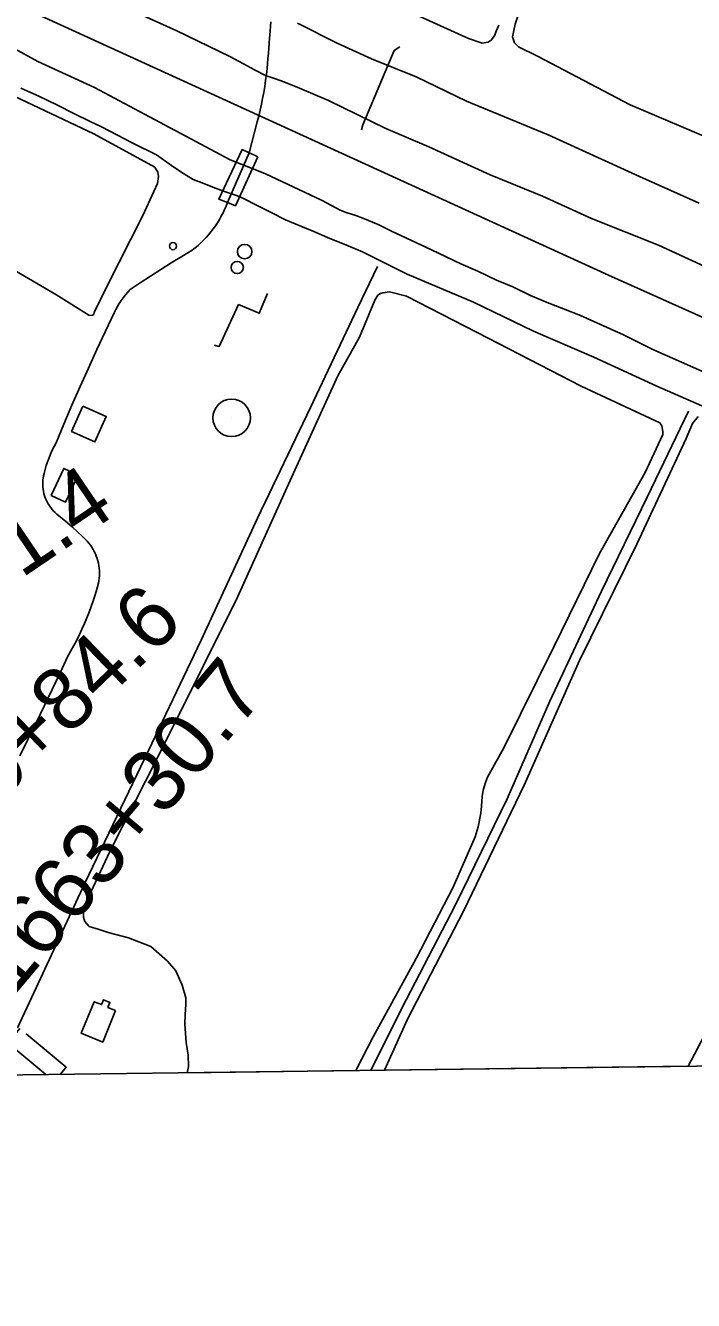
# Model space of a CAD drawing. Extents: x 3734862 to 3772949, y 391520 to 417239.
# Drawn here: x 3766771 to 3767838, y 396853 to 398891 of the extents above; entities that cross this region are included whole.
import ezdxf

# ---------------------------------------------------------------- set-up
doc = ezdxf.new("R2010")
doc.units = 0
for name, color, linetype in [('V-BLDG-OTLN', 7, 'Continuous'), ('V-BRDG-OTLN', 7, 'Continuous'), ('V-DOMW-TANK', 7, 'Continuous'), ('V-GRID-FRAM', 7, 'Continuous'), ('V-LEVE-TOET', 7, 'Continuous'), ('V-ROAD-CNTR', 7, 'Continuous'), ('V-SITE-VEGE', 7, 'Continuous'), ('V-SURV-IDEN', 7, 'Continuous'), ('V-TOPO-SHOR', 7, 'Continuous'), ('V-TOPO-TOWR', 7, 'Continuous'), ('V-UTIL-LINE', 7, 'Continuous')]:
    doc.layers.add(name, color=color, linetype=linetype)

msp = doc.modelspace()

# ---------------------------------------------------------------- linework, layer by layer
at = {"layer": 'V-BLDG-OTLN'}
for points in [[(3766862.7, 398282.6), (3766900, 398266.1), (3766882, 398225.3), (3766844.6, 398241.9)], [(3766855.1, 398172.3), (3766835, 398129), (3766812.1, 398139.7), (3766832.2, 398183)], [(3766915.1, 397316.2), (3766894.4, 397265.8), (3766860.1, 397279.9), (3766880.9, 397330.5), (3766892.4, 397325.8), (3766895.6, 397333.5), (3766906, 397329.3), (3766902.7, 397321.3)]]:
    msp.add_lwpolyline(points, close=True, dxfattribs=at)
at = {"layer": 'V-BRDG-OTLN'}
msp.add_line((3767093.8, 398607.7), (3767128.5, 398687.3), dxfattribs=at)
msp.add_lwpolyline([(3767142.5, 398680.9), (3767106.7, 398602.6), (3767093.8, 398607.7), (3767080.2, 398613.1), (3767117.1, 398692.5), (3767128.5, 398687.3), (3767138.1, 398683)], close=True, dxfattribs=at)
at = {"layer": 'V-DOMW-TANK'}
for centre, radius in [((3767006.7, 398538.2), 5.76), ((3767121.2, 398529.4), 11.6), ((3767109.4, 398504), 9.76)]:
    msp.add_circle(centre, radius, dxfattribs=at)
at = {"layer": 'V-GRID-FRAM'}
msp.add_lwpolyline([(3738832.3, 415033.8), (3770599.2, 415447.4), (3770843.8, 397266.6), (3739061.1, 396852.8), (3738832.3, 415033.8)], dxfattribs=at)
at = {"layer": 'V-LEVE-TOET'}
for points in [[(3766947.7, 398911.8), (3767012.6, 398882.2), (3767097.3, 398841.1), (3767119.5, 398829.7), (3767136.9, 398819.8), (3767155.7, 398810.6), (3767165.6, 398807.1), (3767181.4, 398802), (3767208.7, 398790.9), (3767255, 398771.2), (3767346.8, 398726.2), (3767415.6, 398697), (3767513.4, 398652.4), (3767596.9, 398618), (3767675.6, 398582.5), (3767782.4, 398539.5), (3767884.1, 398492.9)], [(3767205.5, 398894.7), (3767269.2, 398862.4), (3767323.8, 398837.5), (3767395, 398808.7), (3767475.7, 398770), (3767605.9, 398716), (3767751.9, 398649.6), (3767847.3, 398607)]]:
    msp.add_lwpolyline(points, dxfattribs=at)
at = {"layer": 'V-ROAD-CNTR'}
for points in [[(3765561.3, 399764.9), (3765755.5, 399602.6), (3766144.5, 399300.8), (3766783.9, 398911.4), (3767702.3, 398491.7), (3768862.8, 397971.9), (3769048, 397895.2), (3769757.8, 397573.5), (3770042.5, 397441.9), (3770082, 397419.9), (3770108.8, 397401), (3770359.7, 397267.3)], [(3767162.9, 398896.6), (3767161.5, 398875.2), (3767161.1, 398870.8), (3767160.5, 398862.6), (3767159.8, 398854.4), (3767159.2, 398846.3), (3767158.5, 398838.1), (3767157.8, 398830), (3767157, 398822), (3767155.9, 398812.4), (3767155.7, 398810.6), (3767154.6, 398802.9), (3767153.2, 398793.4), (3767151.6, 398783.9), (3767149.8, 398774.4), (3767147.9, 398765), (3767145.9, 398755.5), (3767143.6, 398746.1), (3767141.2, 398736.8), (3767128.5, 398687.3), (3767093.8, 398607.7), (3767091.6, 398602.1), (3767089.2, 398596.6), (3767086.7, 398591.2), (3767083.9, 398585.9), (3767081, 398580.7), (3767077.8, 398575.5), (3767074.5, 398570.5), (3767071.1, 398565.6), (3767067.4, 398560.9), (3767063.6, 398556.3), (3767059.6, 398551.8), (3767055.5, 398547.5), (3767051.2, 398543.3), (3767046.7, 398539.2), (3767042.1, 398535.4), (3767037.4, 398531.7), (3767020.6, 398521.6), (3767003.9, 398511.4), (3766987.4, 398500.9), (3766970.9, 398490.3), (3766954.5, 398479.6), (3766938.3, 398468.6), (3766934.5, 398464.5), (3766930.8, 398460.2), (3766927.3, 398455.8), (3766924, 398451.2)], [(3766758.1, 397288.7), (3766784.3, 397344.6), (3766866.1, 397519.9), (3766961.5, 397719.5), (3767051.6, 397908.5), (3767141.7, 398103.4), (3767226.5, 398280.4), (3767302.3, 398440.3), (3767333.2, 398505.6)], [(3766924, 398451.2), (3766920.9, 398446.5), (3766918, 398441.7), (3766915.3, 398436.8), (3766912.8, 398431.8), (3766898.8, 398402.4), (3766885, 398372.9), (3766871.5, 398343.3), (3766858.2, 398313.6), (3766845.1, 398283.8), (3766832.3, 398253.8), (3766819.8, 398223.8), (3766816.7, 398217.9), (3766813.8, 398212), (3766811.1, 398205.9), (3766808.6, 398199.8), (3766806.4, 398193.6), (3766804.3, 398187.3), (3766802.4, 398180.9), (3766800.8, 398174.5), (3766800, 398171), (3766799.4, 398167.5), (3766798.9, 398164), (3766798.7, 398160.4), (3766798.7, 398156.8), (3766798.9, 398153.2), (3766799.2, 398149.7), (3766799.8, 398146.2), (3766800.6, 398142.7), (3766801.6, 398139.2), (3766802.7, 398135.8), (3766804.1, 398132.5), (3766805.6, 398129.3), (3766807.3, 398126.2)], [(3767323, 397220.8), (3767379.3, 397333.3), (3767458, 397485.1), (3767540.8, 397654.7), (3767608.9, 397810.7), (3767691.1, 397986.9), (3767764.5, 398136.9), (3767830.1, 398274.5)], [(3766807.3, 398126.2), (3766809.2, 398123.1), (3766811.3, 398120.2), (3766813.5, 398117.4), (3766815.9, 398114.7), (3766818.4, 398112.2), (3766821.1, 398109.8), (3766829.5, 398103), (3766837.9, 398096), (3766846.1, 398088.9), (3766854.1, 398081.6), (3766862.1, 398074.1), (3766869.8, 398066.5), (3766872.4, 398063.4), (3766874.8, 398060.2), (3766877, 398056.9), (3766879.1, 398053.5), (3766881, 398050), (3766882.7, 398046.4), (3766884.2, 398042.7), (3766885.6, 398038.9), (3766886.7, 398035.1), (3766887.6, 398031.2), (3766888.4, 398027.2), (3766888.9, 398023.3), (3766889.2, 398019.3), (3766889.3, 398015.3), (3766889.2, 398011.3), (3766888.9, 398007.3), (3766888.4, 398003.3), (3766887.7, 397999.4), (3766885.1, 397990), (3766882.3, 397980.6), (3766879.3, 397971.3), (3766876.1, 397962.1), (3766872.7, 397953), (3766869.1, 397943.9), (3766865.3, 397934.9), (3766861.3, 397926), (3766857.1, 397917.2), (3766852.8, 397908.5), (3766848.2, 397899.9), (3766843.4, 397891.3), (3766838.5, 397882.9), (3766826.2, 397856.1), (3766813.7, 397829.4), (3766801, 397802.7), (3766788.1, 397776.2), (3766775, 397749.7), (3766761.8, 397723.3)], [(3766803.5, 397214), (3766742.7, 397264.8), (3766761.9, 397287.8)], [(3766772.2, 397279.2), (3766836.1, 397225.8), (3766826.5, 397214.3)]]:
    msp.add_lwpolyline(points, dxfattribs=at)
at = {"layer": 'V-SITE-VEGE'}
for p, q in [((3767304.8, 398392.8), (3767329.1, 398451.6)), ((3767329.1, 398451.6), (3767333.8, 398460)), ((3767333.8, 398460), (3767338, 398462.3)), ((3767338, 398462.3), (3767342.2, 398463.5)), ((3767342.2, 398463.5), (3767352.8, 398465.3)), ((3767352.8, 398465.3), (3767379.6, 398458.2)), ((3767379.6, 398458.2), (3767510.3, 398391.2)), ((3767269.9, 398330.7), (3767304.8, 398392.8)), ((3767510.3, 398391.2), (3767658.8, 398314.2)), ((3767198.8, 398174.4), (3767269.9, 398330.7)), ((3767658.8, 398314.2), (3767784.8, 398255.5)), ((3767784.8, 398255.5), (3767787.8, 398250.7)), ((3767787.8, 398250.7), (3767789.6, 398241.8)), ((3767826.4, 398230.6), (3767836.5, 398254.4)), ((3767836.5, 398254.4), (3767846, 398265.7)), ((3767747.6, 398061.8), (3767826.4, 398230.6)), ((3767789.6, 398237.1), (3767761.1, 398176.5)), ((3767789.6, 398241.8), (3767789.6, 398237.1)), ((3767109.8, 397977.3), (3767198.8, 398174.4)), ((3767761.1, 398176.5), (3767688.2, 398046.9)), ((3767688.2, 398046.9), (3767615.3, 397897.8)), ((3767656.3, 397875.9), (3767747.6, 398061.8)), ((3767000.7, 397757.4), (3767109.8, 397977.3)), ((3767615.3, 397897.8), (3767535.3, 397736.2)), ((3767567.6, 397676.5), (3767656.3, 397875.9)), ((3766905.9, 397570.8), (3767000.7, 397757.4)), ((3767535.3, 397736.2), (3767509.2, 397689.2)), ((3767471, 397475), (3767567.6, 397676.5)), ((3767506.2, 397680.9), (3767502.1, 397668.5)), ((3767509.2, 397689.2), (3767506.2, 397680.9)), ((3767500.9, 397658.4), (3767499.7, 397642.9)), ((3767502.1, 397668.5), (3767500.9, 397658.4)), ((3767499.7, 397642.9), (3767498.5, 397631.6)), ((3767498.5, 397631.6), (3767494.4, 397609.7)), ((3767494.4, 397609.7), (3767489.7, 397594.2)), ((3767489.7, 397594.2), (3767454.1, 397513.4)), ((3766864.4, 397481.7), (3766905.9, 397570.8)), ((3767454.1, 397513.4), (3767395.4, 397399.3)), ((3766863.8, 397465.1), (3766864.4, 397481.7)), ((3767381.5, 397302.7), (3767471, 397475)), ((3766865.6, 397458.6), (3766863.8, 397465.1)), ((3766872.8, 397450.5), (3766865.6, 397458.6)), ((3766887, 397446.3), (3766872.8, 397450.5)), ((3766903, 397441), (3766887, 397446.3)), ((3766935.7, 397432.7), (3766903, 397441)), ((3766971.4, 397418.5), (3766935.7, 397432.7)), ((3766998.1, 397395.4), (3766971.4, 397418.5)), ((3767011.2, 397379.9), (3766998.1, 397395.4)), ((3767395.4, 397399.3), (3767326.7, 397274.5)), ((3767021.3, 397356.8), (3767011.2, 397379.9)), ((3767027.3, 397336.6), (3767021.3, 397356.8)), ((3767027.3, 397325.9), (3767027.3, 397336.6)), ((3767025.5, 397294.4), (3767026.1, 397309.9)), ((3767026.1, 397309.9), (3767027.3, 397325.9)), ((3767027.9, 397265.3), (3767025.5, 397294.4)), ((3767344.4, 397221), (3767381.5, 397302.7)), ((3767869.7, 397303.2), (3767829.6, 397227.4)), ((3767326.7, 397274.5), (3767298.7, 397220.4)), ((3767030.9, 397245.2), (3767027.9, 397265.3)), ((3767031.5, 397226.7), (3767030.9, 397245.2)), ((3767029.5, 397216.9), (3767031.5, 397226.7)), ((3767298.7, 397220.4), (3767029.5, 397216.9)), ((3767829.6, 397227.4), (3767344.4, 397221))]:
    msp.add_line(p, q, dxfattribs=at)
msp.add_lwpolyline([(3766743.9, 398782.3), (3766880.3, 398717.8), (3766977.6, 398664.5), (3766982.3, 398656.2), (3766983.5, 398649.7), (3766981.7, 398638.4), (3766958.7, 398587.4), (3766901.3, 398474.7), (3766880.6, 398432), (3766880, 398429.1), (3766877, 398427.3), (3766872.3, 398427.9), (3766819.5, 398461), (3766709.7, 398524.9)], dxfattribs=at)
at = {"layer": 'V-TOPO-SHOR'}
for points in [[(3767916.5, 398691.2), (3767892.1, 398699.5), (3767861.2, 398711.3), (3767737.1, 398764.1), (3767589.1, 398841.7), (3767558.8, 398856.5), (3767552.3, 398863.1), (3767549.3, 398872.6), (3767553.4, 398892.8), (3767559.3, 398910.6), (3767560.5, 398923.1), (3767560.5, 398942.7), (3767560.5, 398961.1), (3767564.6, 398981.3), (3767572.3, 399005.6), (3767600.2, 399062.7), (3767644.6, 399155.4), (3767693.8, 399259.3), (3767740, 399373.4), (3767748.3, 399394.8), (3767747.7, 399400.1), (3767745.9, 399401.3), (3767740, 399401.9), (3767735.8, 399401.3)], [(3767527.3, 398891.6), (3767523.1, 398882), (3767520.8, 398875.5), (3767515.4, 398867.8), (3767510.1, 398864.2), (3767500.6, 398862.4), (3767478.6, 398870.1), (3767400.2, 398905.7)], [(3766709.9, 398877.7), (3766791, 398833.1), (3766881.5, 398791.5), (3766969.1, 398744.6), (3767051.4, 398701.2), (3767097.8, 398676), (3767153.6, 398654.3), (3767245.3, 398610.9), (3767274, 398595.7), (3767283.5, 398592.2), (3767298.7, 398586.9), (3767309.9, 398582.8), (3767334.6, 398572.9), (3767355.7, 398562.3), (3767388, 398547.1), (3767419.8, 398532.4), (3767466.8, 398510.1), (3767493.8, 398498.4), (3767523.8, 398483.8), (3767549.6, 398473.2), (3767577.8, 398459.1), (3767604.3, 398448), (3767630.7, 398438.1), (3767657.7, 398427.5), (3767726.5, 398396.4), (3767773.5, 398373), (3767819.3, 398352.5), (3767861, 398334.3)], [(3766763.5, 398790.8), (3766792.3, 398777.9), (3766821.1, 398763.8), (3766849.3, 398749.8), (3766874.5, 398737.5), (3766892.7, 398728.7), (3766942.7, 398702.9), (3766980.3, 398684.1), (3767004.4, 398667.1), (3767020.9, 398656), (3767039.1, 398644.8), (3767053.2, 398639.5), (3767070.2, 398632.5), (3767087.3, 398626.1), (3767109.6, 398618.5), (3767120.2, 398613.8), (3767139, 398604.4), (3767162.5, 398592.7), (3767186.6, 398580.3), (3767208.3, 398571), (3767231.8, 398561.6), (3767253.5, 398552.2), (3767286.4, 398538.7), (3767309.4, 398528.8), (3767327.6, 398520)], [(3767327.6, 398520), (3767381, 398493.6), (3767486.8, 398448.5), (3767582.6, 398402.2), (3767678.9, 398360.6), (3767780, 398314.3), (3767898.1, 398262.7), (3768011.5, 398218.2), (3768030.3, 398211.7), (3768042.7, 398203.5), (3768067.3, 398185.9), (3768083.2, 398173.6), (3768096.7, 398164.8), (3768112, 398157.8), (3768130.2, 398150.7), (3768152.5, 398143.7), (3768169.6, 398137.9)]]:
    msp.add_lwpolyline(points, dxfattribs=at)
at = {"layer": 'V-TOPO-TOWR'}
msp.add_line((3767100.4, 398263.7), (3767100.4, 398263.7), dxfattribs=at)
msp.add_circle((3767100.4, 398263.7), 30, dxfattribs=at)
at = {"layer": 'V-UTIL-LINE'}
for points in [[(3767369.1, 398857), (3767360.2, 398851.1), (3767309.9, 398732.1), (3767307.7, 398724)], [(3767072.3, 398379.7), (3767080.4, 398377.8), (3767111.5, 398444.8), (3767144.6, 398431), (3767157.7, 398462.6)]]:
    msp.add_lwpolyline(points, dxfattribs=at)

# ---------------------------------------------------------------- texts
at = {"layer": 'V-SURV-IDEN'}
for s, rotation, p in [('1656+31.4', 34.1188, (3766391.8, 397754)), ('1660+84.6', 43.8792, (3766567.7, 397493.1)), ('1663+30.7', 50.0247, (3766750.2, 397336.3))]:
    msp.add_text(s, height=100, rotation=rotation, dxfattribs=at).set_placement(p)

doc.saveas('drawing.dxf')
